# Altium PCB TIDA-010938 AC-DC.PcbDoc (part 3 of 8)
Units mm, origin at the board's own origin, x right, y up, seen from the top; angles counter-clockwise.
Board outline 280 x 180.15 mm, 4 copper layers (Top Layer, Layer 1, Layer 2, Bottom Layer), stack 1.787 mm thick; 723 components, 427 nets, 2244 pads, 2295 vias.
Unrouted connection lines stored in the file: 17.
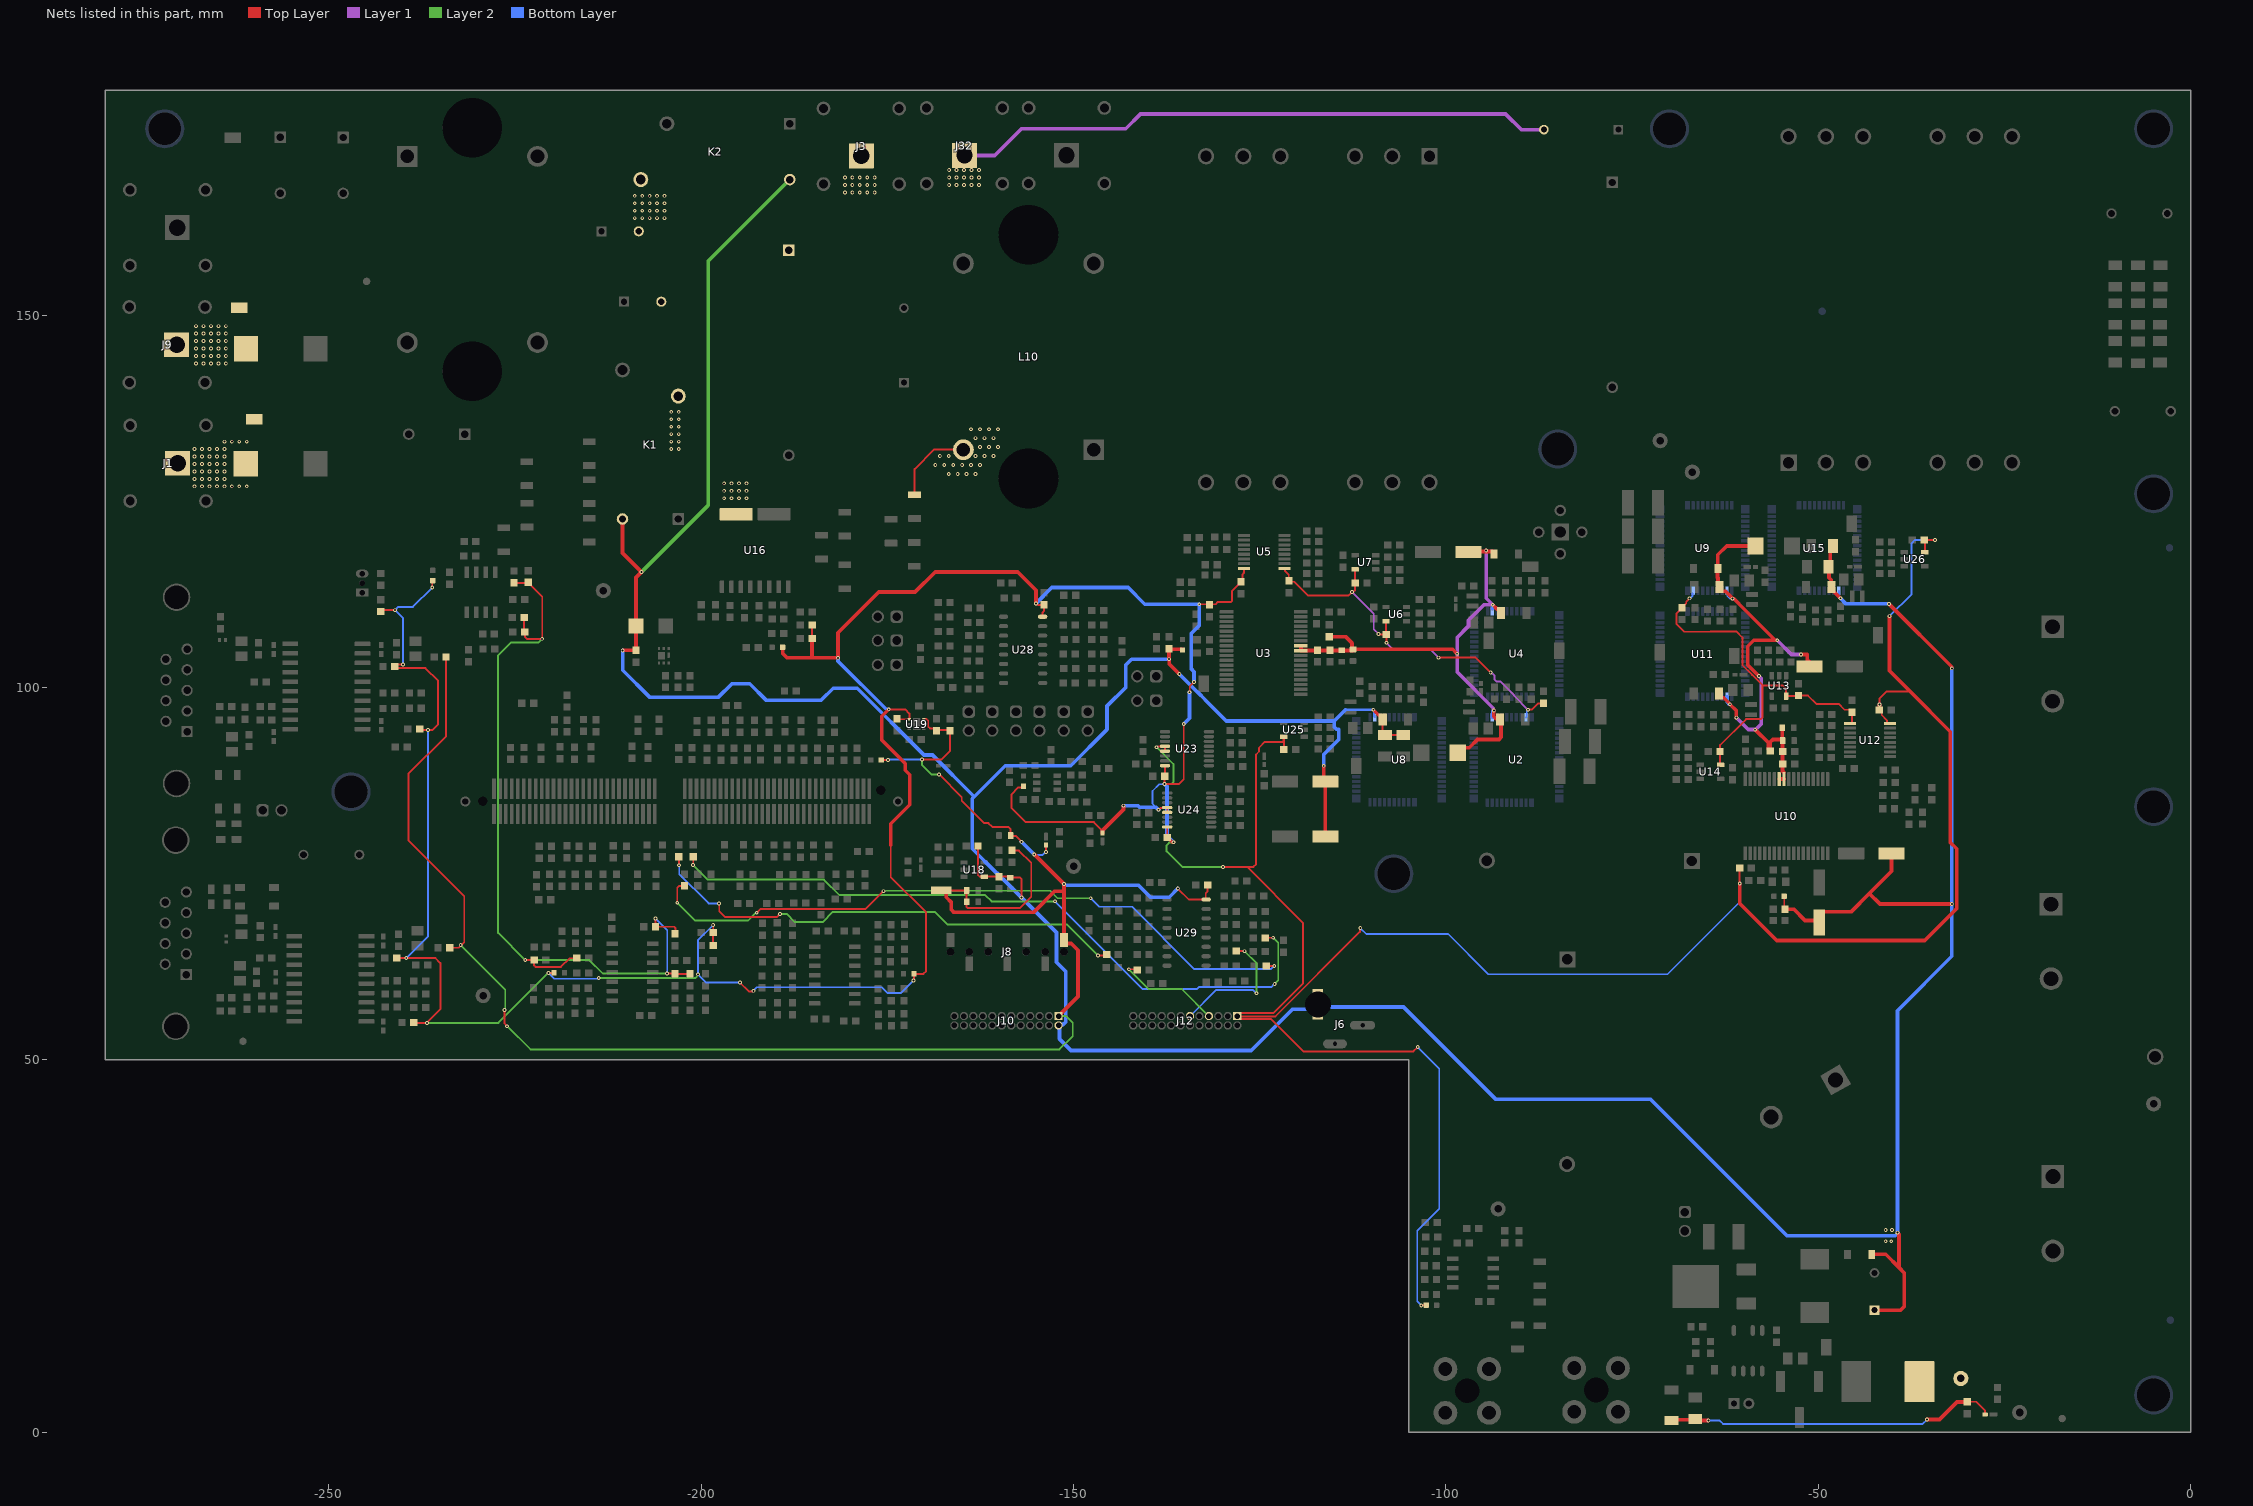
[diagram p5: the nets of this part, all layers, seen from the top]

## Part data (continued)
C217 C221 C233 C237: library part CMP-0007220-4, "CAP, CERM, 47 pF, 50 V, +/- 5%, C0G/NP0, 0603", Cap_Case=0603, Manufacturer=MuRata, Supplier Part Number 1=490-1419-1-ND, TempCo=C0G/NP0, Tolerance_%=5%, Value1=Unknown, Value2=50V, ValueDisplayed=47pF
C220 C236: library part CMP-0006987-4, "CAP, CERM, 4700 pF, 50 V, +/- 10%, X7R, 0603", Cap_Case=0603, Manufacturer=Kemet, Supplier Part Number 1=399-5337-1-ND, TempCo=X7R, Tolerance_%=10%, Value1=Unknown, Value2=50V, ValueDisplayed=4700pF
C241 C242: library part CMP-0037193-1, "5 µF Film Capacitor 900V Polypropylene (PP), Metallized Radial", Digikey Part Number=399-C4AKOBU4500A31J-ND, Manufacturer=Kemet, Mouser Part Number=80-C4AKOBU4500A31J, Operating Temperature Range="-55°C to +135°C", Tolerance_%=5%, ValueDisplayed=5uF
C243 C244: library part CMP-0009613-2, "CAP, CERM, 2200 pF, 300 V, +/- 20%, E, TH, 2- Leads, Body 9x7mm, Pin Spacing 7.5mm", Cap_Case=9x7x9mm, Manufacturer=MuRata, Supplier Part Number 1=DE6E3KJ222MN3A-ND, TempCo=E, Tolerance_%=20%, Value1=Unknown, Value2=300V, ValueDisplayed=2200pF
D1 D7: library part CMP-0095009-1, "Diode Silicon Carbide Schottky 1200 V 2A (DC) Surface Mount DO-214AA", Digikey Part Number=1242-1170-1-ND, Forward Current=2A, Manufacturer="GeneSiC Semiconductor", Max Surge Forward Current=20A, Mouser Part Number=905-GB02SLT12-214, Operating Temperature Range="-55°C to +175°C", Peak Reverse Current=1uA, ValueDisplayed=122pF
D2 D8 D19: library part CMP-0005769-4, "Diode, Zener, 16 V, 500 mW, AEC-Q101, SOD-123", Manufacturer="Diodes Inc.", Power_W=500mW, Value1=0.5W
D4 D10 D16 D17 D18 D23 D24 D25 D26 D27 D28: library part CMP-0093310-1, "Standard LEDs - SMD Green TOPLED E 1608", Color=Green, Forward Current=2mA, Manufacturer="Osram Opto", Mouser Part Number=720-KGDELLS122A4849, Operating Temperature Range="-40°C to +110°C"
D13: library part CMP-0028389-2, "Diode, Schottky, 60 V, 1 A, SMA", Manufacturer="Diodes Inc.", Value1=1A, Value2=0.7V
D14: library part CMP-0029001-2, "Diode, Ultrafast, 100 V, 0.15 A, SOD-123", Manufacturer="Diodes Inc.", Value1=0.15A, Value2=1.25V
D15: library part CMP-0029162-2, "Diode, Ultrafast, 600 V, 1 A, AEC-Q101, SMAF", Manufacturer="Fairchild Semiconductor", Value1=1A, Value2=1.7V
D20: library part CMP-0076883-2, "Diode, Switching, 800 V, 3 A, SMC", Manufacturer=Vishay-Semiconductor, Value1=3A, Value2=1.3V
F1 F2: library part CMP-0122960-1, "25 A 250 V AC 80 V DC Fuse Board Mount (Cartridge Style Excluded) Surface Mount 2-SMD, Square End Block", Digikey Part Number=SF-3812F2500T-2CT-ND, Fuse Current=25A, Fuse Interrupt Dc Current=130A, Manufacturer=Bourns, Mouser Part Number=652-SF-3812F2500T-2, Operating Temperature Range="-55°C to +125°C"
FB2 FB4 FB6 FB7 FB8 FB9 FB11 FB12 FB14: library part CMP-0037505-1, "600 Ohms @ 100 MHz 1 Power, Signal Line Ferrite Bead 0603 (1608 Metric) 1A 200mOhm", Digikey Part Number=MH1608-601YCT-ND, Impedance At Frequency="600Ω @ 100MHz", Manufacturer=Bourns, Mouser Part Number=652-MH1608-601Y, Operating Temperature Range="-55°C to +125°C", Test Frequency=100MHz, Tolerance_%=25%
FB18 FB23: library part CMP-0041881-1, "Chip Ferrite Bead, 0402, 330Ω @ 100MHz, 0.205Ω, 25%, 1.1A", Impedance At Frequency="330Ω @ 100MHz", Manufacturer=Murata, Operating Temperature Range="-55°C to +125°C", Test Frequency=100MHz, Tolerance_%=25%
FID1 FID2 FID3 FID4 FID5 FID6: library part CMP-0077181-1, "Fiducial mark.  There is nothing to buy or mount.", Manufacturer=N/A
J1 J32: library part CMP-0098295-2, "Banana Test Connector, 4mm, Socket, PCB Mount, 24 A, 1 kV, Gold Plated Contacts, Blue", Current_A=24A, Manufacturer="CLIFF Electronic Components", Operating Temperature Range="-40°C to +80°C", Voltage_V=1kV
J2 J31: library part CMP-0098294-2, "Banana Test Connector, Socket, PCB Mount, 24 A, 1 kV, Gold Plated Contacts, Green", Current_A=24A, Digikey Part Number=4654-FCR7350G-ND, Manufacturer="CLIFF Electronic Components", Operating Temperature Range="-40°C to +80°C", Voltage_V=1kV
J3 J9: library part CMP-0032021-2, "Banana Jack Connector Standard Banana Solder Black", Current_A=24A, Digikey Part Number=4654-FCR7350B-ND, Manufacturer="CLIFF Electronic Components", Operating Temperature Range="-40°C to +80°C", Voltage_V=1kV
J4 J5 J7 J13 J14 J16 J20 J21 J22 J23 J24 J25 J26: library part CMP-0054794-2, "Header, 2.54 mm, 2x1, Gold, TH", Color=Black, Manufacturer="Wurth Elektronik", Supplier Part Number 1=732-5315-ND
J6: library part CMP-0040211-1, "Power Barrel Connector Jack 2.10mm ID (0.083\"), 5.50mm OD (0.217\") Through Hole", Current_A=3A, Digikey Part Number=732-5931-ND, Manufacturer="Wurth Electronics", Mouser Part Number=710-694106402002, Operating Temperature Range="-40°C to +85°C", Voltage_V=30V
J8: library part CMP-0095208-1, "7 Position Receptacle, Bottom Entry Connector 0.100\" (2.54mm) Surface Mount Gold", Current_A=5.2A, Digikey Part Number=SSM-107-L-SV-BE-ND, Manufacturer=Samtec, Mouser Part Number=200-SSM107LSVBE, Operating Temperature Range="-55°C to +125°C", Voltage_V=572V
J10 J12: library part CMP-0003796-1, "Conn Shrouded Header (4 Sides) HDR 24 POS 1.27mm Solder ST Top Entry Thru-Hole Tube", Digikey Part Number=SHF-112-01-L-D-TH-ND, Manufacturer=Samtec, Mouser Part Number=200-SHF11201LDTH, Operating Temperature Range="-55°C to +125°C"
J11: library part CMP-0003814-2, "C2000 controlCARD-120HSEC connector, SMT", Manufacturer=Samtec
J15 J17: library part CMP-0054820-2, "Receptacle, D-Sub, 9 Position, R/A, TH", Color=Black, Current_A=3A, Manufacturer="Wurth Elektronik", Supplier Part Number 1=16T0655, Voltage_V=125V
J18 J19: library part CMP-0078526-1, "Power Element Bush, M3, TH", Current_A=50A, Manufacturer="Wurth Elektronik", Supplier Part Number 1=732-10882-1-ND
J27: library part CMP-0089221-2, "Test Clip, Lead, Probe Adapter for use with LeCroy Passive Probes", Digikey Part Number=PK007-015-ND, Manufacturer="Teledyne Lecroy", Mouser Part Number=940-PK007-015, Operating Temperature Range=to
K1 K2: library part CMP-0093993-1, "General Purpose Relay SPST-NO (1 Form A) 12VDC Coil Through Hole", Coil Current_A=44.1mA, Coil Power_W=530mW, Coil Resistance=272Ω, Coil Voltage_VDC=12V, Contact Rating_A=20A, Digikey Part Number=39-G5PZ-1A-EDC12-ND, Manufacturer=Omron, Mouser Part Number=653-G5PZ-1A-EDC12, Operating Temperature Range="-40°C to +70°C"
L1 L4: library part CMP-0123013-1, "PFC Inductor 87µH ±10% 35A 13 mΩ", Manufacturer=Bourns, Operating Temperature Range="-40°C to +125°C", Test Frequency=100kHz, Tolerance_%=10%
L2 L3 L5 L6 L7 L9: library part CMP-0089347-1, "4.7µH Unshielded Inductor 1.1A 426mOhm Max 0806 (2016 Metric)", Digikey Part Number=2037-SDEM20161T-4R7MSCT-ND, Manufacturer=Cyntec, Operating Temperature Range="-55°C to +125°C", Test Frequency=1MHz, Tolerance_%=20%
L8 L12 L16 L17: library part CMP-0003349-2, "Ferrite Bead, 1500 ohm @ 100 MHz, 0.5 A, 0603", Manufacturer=MuRata, Supplier Part Number 1=490-5216-1-ND, Value1="0.5 ohm", Value2=0.5A, ValueDisplayed="1500 ohm"
L10 L11: library part CMP-0123012-1, "Common Mode Choke 4mH ±30%", Manufacturer="Kaschke Components", Operating Temperature Range="-25°C to +125°C", Tolerance_%=30%
L13: library part CMP-0123259-1, "Shielded SMD Power Inductor 220uH 2A 240mOhm 12.0x12.0x10.0mm SMT", Manufacturer=Bourns, Operating Temperature Range="-55°C to +150°C", Test Frequency=1kHz, Tolerance_%=10%
L14: library part CMP-0056744-1, "Inductor, Drum Core, Ferrite, 10 uH, 0.88 A, 0.276 ohm, SMD", Manufacturer=Bourns, Supplier Part Number 1=SRN3015-100MCT-ND, Value1="0.276 ohm", Value2=0.88A, ValueDisplayed=10uH
L25 L31: library part CMP-0084086-1, "100µH @ 100kHz 2 Line Common Mode Choke Surface Mount 5.8 kOhms @ 10MHz 150mA DCR 2Ohm", Digikey Part Number=445-3959-1-ND, Impedance At Frequency="5800Ω @ 10MHz", Manufacturer=TDK, Mouser Part Number=810-ACT45B1012PTL003, Operating Temperature Range="-40°C to +150°C", Test Frequency=100kHz, Tolerance_%=+50/-30%
LBL1: library part CMP-0003625-1, "Thermal Transfer Printable Labels, 0.650\" W x 0.200\" H - 10,000 per roll", Manufacturer=Brady, Supplier Part Number 1=97C5133
LOGO1: library part CMP-0074837-1, "IEC 61010-1 Hot Surface Warning"
LOGO2: library part CMP-0074835-1, "IEC 61010-1 High Voltage Warning"
Logo3: library part CMP-0074844-1
Logo5: library part CMP-0074847-1, "FCC_disclaimer"
Logo6: library part CMP-0074769-1
MP1 MP2 MP3 MP4 MP5 MP6 MP7 MP8 MP12: library part CMP-0040203-1, "Round Spacer Unthreaded Steel 0.059\" (1.50mm)", Digikey Part Number=732-7071-1-ND, Manufacturer="Wurth Electronics", Mouser Part Number=710-9774015960R, Operating Temperature Range="-55°C to +150°C"
Q1: library part CMP-0076725-1, "30-V N-Channel NexFET™ Power MOSFET", Manufacturer="Texas Instruments"
Q2: library part CMP-0001278-3, "MOSFET, N-CH, 800 V, 2.5 A, DPAK", Alternate Manufacturer=None, Manufacturer=STMicroelectronics, Supplier Part Number 1=497-7968-1-ND, Value2="19 nC"
R1 R8 R9 R18 R19 R24 R25 R26 R27 R28 R29 R31 R32 R35 R37 R38 R39 R58 R59 R61 R62 R63 R64 R65 R66 R69 R71 R72 R73 R83 R86 R87 R88 R120 R121 R134 R140 R141 R144 R146 R148 R150 R151 R152 R154 R160 R161 R169 R170 R175 R259 R260 R263 R264 R265 R267 R268 R270 R272 R273 R274 R276 R278 R279 R281 R282 R284 R286 R311 R314 R319 R320 R323: library part CMP-0023572-3, "RES, 56, 0.1%, 0.1 W, 0603", Manufacturer="Susumu Co Ltd", Power_W=100mW, Supplier Part Number 1=RG16P56.0BCT-ND, TempCo="25 ppm/C", Tolerance_%=0.1%, Value2=0.1W, Value_Code=56R0, ValueDisplayed=56
R2 R3 R4 R97 R119 R136 R137 R138 R139 R142 R143 R145 R156 R159 R163 R165: library part CMP-0024479-2, "RES, 7.32 k, 0.1%, 0.1 W, 0603", Manufacturer="Yageo America", Power_W=100mW, TempCo="25 ppm/C", Tolerance_%=0.1%, Value2=0.1W, Value_Code=7k32, ValueDisplayed=7.32k
R5 R23 R33 R34 R36 R50 R68 R99 R125 R126 R130 R131 R133 R135 R147 R149 R153 R155 R157 R158 R162 R164 R166 R167 R168 R171 R172 R173 R237 R238 R239 R252 R253 R254 R256 R297 R298 R299 R300 R301 R302 R303 R304 R305 R306 R307 R308 R310 R318 R328 R329 R330 R331 R332 R335 R336 R337 R338: library part CMP-0023404-3, "RES, 10.0 k, 0.1%, 0.1 W, 0603", Manufacturer="Susumu Co Ltd", Power_W=100mW, Supplier Part Number 1=RG16P10.0KBCT-ND, TempCo="25 ppm/C", Tolerance_%=0.1%, Value2=0.1W, Value_Code=10k0, ValueDisplayed=10.0k
R6: library part CMP-0089579-1, "SENSOR PTC 10K OHM 1% TO92S", Digikey Part Number=296-TMP6131LPGMCT-ND, Manufacturer="Texas Instruments", Max Current=400uA, Mouser Part Number=595-TMP6131LPGM, Operating Temperature Range="-40°C to +150°C", TempCo=6400ppm/°C, Tolerance_%=1%
R7 R41 R53 R55: library part CMP-0018694-3, "RES, 4.7, 5%, 0.75 W, AEC-Q200 Grade 0, 1206", Manufacturer=Vishay-Dale, Power_W=750mW, Supplier Part Number 1=541-4.7UACT-ND, TempCo="200 ppm/C", Tolerance_%=5%, Value2=0.75W, Value_Code=4R70, ValueDisplayed=4.7
R10 R30 R40 R44 R60 R74: library part CMP-0023577-3, "RES, 56.0 k, 0.1%, 0.1 W, 0603", Manufacturer="Susumu Co Ltd", Power_W=100mW, Supplier Part Number 1=RG16P56.0KBCT-ND, TempCo="25 ppm/C", Tolerance_%=0.1%, Value2=0.1W, Value_Code=56k0, ValueDisplayed=56.0k
R11 R13 R46 R47: library part CMP-0022685-3, "RES, 12.0 k, 1%, 0.1 W, 0603", Manufacturer=Panasonic, Power_W=100mW, Supplier Part Number 1=P12.0KHCT-ND, TempCo="100 ppm/C", Tolerance_%=1%, Value2=0.1W, Value_Code=12k0, ValueDisplayed=12.0k
R12 R45: library part CMP-0025200-2, "RES, 38.8 k, 0.5%, 0.1 W, 0603", Manufacturer="Yageo America", Power_W=100mW, TempCo="50 ppm/C", Tolerance_%=0.5%, Value2=0.1W, Value_Code=38k8, ValueDisplayed=38.8k
R14 R48: library part CMP-0023076-5, "RES, 3.01 k, 1%, 0.1 W, 0603", Manufacturer=Yageo, Power_W=100mW, Supplier Part Number 1=311-3.01KHRCT-ND, TempCo="100 ppm/C", Tolerance_%=1%, Value2=0.1W, Value_Code=3k01, ValueDisplayed=3.01k
R15 R49 R84 R85 R90 R104 R105: library part CMP-0023404-1, "RES, 10.0 k, 0.1%, 0.1 W, 0603", Manufacturer="Susumu Co Ltd", Power_W=100mW, Supplier Part Number 1=RG16P10.0KBCT-ND, TempCo="25 ppm/C", Tolerance_%=0.1%, Value2=0.1W, Value_Code=10k0, ValueDisplayed=10.0k
R16: library part CMP-0025771-4, "RES, 2.7 k, 5%, 0.1 W, AEC-Q200 Grade 0, 0603", Manufacturer=Vishay-Dale, Power_W=100mW, Supplier Part Number 1=541-2.7KGCT-ND, TempCo="200 ppm/C", Tolerance_%=5%, Value2=0.1W, Value_Code=2k70, ValueDisplayed=2.7k
R17 R42 R43 R51 R52 R100 R115: library part CMP-0025933-5, "RES, 5.6 k, 5%, 0.1 W, 0603", Manufacturer=Yageo, Power_W=100mW, Supplier Part Number 1=311-5.6KGRCT-ND, TempCo="100 ppm/C", Tolerance_%=5%, Value2=0.1W, Value_Code=5k60, ValueDisplayed=5.6k
R20 R21 R22 R54 R56 R57 R67 R174 R176 R177 R178 R179 R180 R181 R182 R183 R184 R186 R187 R188 R189 R190 R191 R192 R193 R194 R195 R196 R197 R198 R199 R200 R201 R202 R203 R204 R205 R206 R207 R208 R209 R210 R211 R212 R213 R214 R215 R216 R217 R218 R219 R220 R221 R222 R223 R224 R225 R226 R227 R228 R229 R230 R231 R232 R233 R234 R236 R240 R241 R242 R243 R244 R245 R246 R247 R248 R249 R250: library part CMP-0081973-1, "RES, 0, 0%, 0.25 W, AEC-Q200 Grade 0, 0603", Manufacturer=Vishay-Dale, Power_W=250mW, Supplier Part Number 1=541-2779-1-ND, Tolerance_%=0%, Value2=0.25W, Value_Code=0
R70 R76 R102: library part CMP-0025936-5, "RES, 680, 5%, 0.1 W, 0603", Manufacturer=Yageo, Power_W=100mW, Supplier Part Number 1=311-680GRCT-ND, TempCo="100 ppm/C", Tolerance_%=5%, Value2=0.1W, Value_Code=680R, ValueDisplayed=680
R75 R114: library part CMP-0097004-1, "PTCEL Series 500 V 60 Ohm ±30 % Radial Inrush Current Limiter PTC Thermistor", Digikey Part Number=BC3317-ND, Hold Current=120mA, Manufacturer="Vishay Bccomponents", Mouser Part Number=594-PTCEL13R600LBE, Operating Temperature Range="-40°C to +105°C", Tolerance_%=30%
R77 R79 R80 R185 R235 R290 R291 R326 R327: library part CMP-0017399-3, "RES, 169 k, 1%, 0.25 W, AEC-Q200 Grade 0, 1206", Manufacturer=Panasonic, Power_W=250mW, Supplier Part Number 1=P169KFCT-ND, TempCo="100 ppm/C", Tolerance_%=1%, Value2=0.25W, Value_Code=169k
R78 R81 R82: library part CMP-0096768-1, "5 kA Varistor 1 Circuit Through Hole Disc 17mm", Clamping Voltage=730V, Digikey Part Number=118-ISOM5-275-B-L2-ND, Manufacturer=Bourns, Mouser Part Number=652-ISOM5-275-B-L2, Operating Temperature Range="-40°C to +125°C", ValueDisplayed=40pF
R89: library part CMP-0024912-2, "RES, 200, 0.5%, 0.1 W, 0603", Manufacturer="Yageo America", Power_W=100mW, TempCo="50 ppm/C", Tolerance_%=0.5%, Value2=0.1W, Value_Code=200R, ValueDisplayed=200
R91: library part CMP-0024274-3, "RES, 48.1 k, 0.1%, 0.1 W, 0603", Manufacturer="Yageo America", Power_W=100mW, TempCo="25 ppm/C", Tolerance_%=0.1%, Value2=0.1W, Value_Code=48k1, ValueDisplayed=48.1k
R92: library part CMP-0025444-3, "RES, 5.76 k, 0.5%, 0.1 W, 0603", Manufacturer="Yageo America", Power_W=100mW, TempCo="50 ppm/C", Tolerance_%=0.5%, Value2=0.1W, Value_Code=5k76, ValueDisplayed=5.76k
R93: library part CMP-0023520-3, "RES, 33.0 k, 0.1%, 0.1 W, 0603", Manufacturer="Susumu Co Ltd", Power_W=100mW, Supplier Part Number 1=RG16P33.0KBCT-ND, TempCo="25 ppm/C", Tolerance_%=0.1%, Value2=0.1W, Value_Code=33k0, ValueDisplayed=33.0k
R94: library part CMP-0017008-3, "RES, 475 k, 1%, 0.25 W, AEC-Q200 Grade 0, 1206", Manufacturer=Vishay-Dale, Power_W=250mW, Supplier Part Number 1=541-475KFCT-ND, TempCo="100 ppm/C", Tolerance_%=1%, Value2=0.25W, Value_Code=475k
R95: library part CMP-0024711-2, "RES, 15.6 k, 0.5%, 0.1 W, 0603", Manufacturer="Yageo America", Power_W=100mW, TempCo="50 ppm/C", Tolerance_%=0.5%, Value2=0.1W, Value_Code=15k6, ValueDisplayed=15.6k
R96: library part CMP-0025116-2, "RES, 301, 0.5%, 0.1 W, 0603", Manufacturer="Yageo America", Power_W=100mW, TempCo="50 ppm/C", Tolerance_%=0.5%, Value2=0.1W, Value_Code=301R, ValueDisplayed=301
R98: library part CMP-0021846-2, "RES, 0.1, 1%, 0.125 W, 0805", Manufacturer=Panasonic, Power_W=125mW, Supplier Part Number 1=15R1493, TempCo="250 ppm/C", Tolerance_%=1%, Value2=0.125W, Value_Code=R100, ValueDisplayed=0.1
R101: library part CMP-0025877-3, "RES, 1.5 k, 5%, 0.1 W, AEC-Q200 Grade 0, 0603", Manufacturer=Panasonic, Power_W=100mW, Supplier Part Number 1=P1.5KGCT-ND, TempCo="200 ppm/C", Tolerance_%=5%, Value2=0.1W, Value_Code=1k50, ValueDisplayed=1.5k
R103: library part CMP-0023638-3, "RES, 105 k, 0.1%, 0.1 W, 0603", Manufacturer="Yageo America", Power_W=100mW, TempCo="25 ppm/C", Tolerance_%=0.1%, Value2=0.1W, Value_Code=105k
R106: library part CMP-0024922-3, "RES, 20.0 k, 0.5%, 0.1 W, 0603", Manufacturer="Yageo America", Power_W=100mW, TempCo="50 ppm/C", Tolerance_%=0.5%, Value2=0.1W, Value_Code=20k0, ValueDisplayed=20.0k
R107: library part CMP-0025733-4, "RES, 1.5 k, 5%, 0.1 W, AEC-Q200 Grade 0, 0603", Manufacturer=Vishay-Dale, Power_W=100mW, Supplier Part Number 1=541-1.5KGCT-ND, TempCo="200 ppm/C", Tolerance_%=5%, Value2=0.1W, Value_Code=1k50, ValueDisplayed=1.5k
R108 R109 R110: library part CMP-0018815-2, "RES, 560 k, 0.1%, 1 W, 1206", Manufacturer="Vishay Draloric", Power_W=1W, Supplier Part Number 1=541-2316-1-ND, TempCo="25 ppm/C", Tolerance_%=0.1%, Value_Code=560k
R111 R112 R113 R116 R117 R118 R122 R123 R124 R127 R128 R129: library part CMP-0018805-2, "RES, 1.00 M, 0.1%, 1 W, 1206", Manufacturer="Vishay Draloric", Power_W=1W, Supplier Part Number 1=541-2320-1-ND, TempCo="25 ppm/C", Tolerance_%=0.1%, Value_Code=1M00, ValueDisplayed=1.00M
R132: library part CMP-0089217-1, "100 kOhms 0.25W, 1/4W Gull Wing Surface Mount Trimmer Potentiometer Cermet 12 Turn Top Adjustment", Digikey Part Number=3269W-1-104LF-ND, Manufacturer=Bourns, Mouser Part Number=652-3269W-1-104LF, Operating Temperature Range="-65°C to +150°C", Power_W=250mW, TempCo=100ppm/°C, Tolerance_%=10%
R280 R287 R288 R289: library part CMP-0025431-3, "RES, 59.7, 0.5%, 0.1 W, 0603", Manufacturer="Yageo America", Power_W=100mW, TempCo="50 ppm/C", Tolerance_%=0.5%, Value2=0.1W, Value_Code=59R7, ValueDisplayed=59.7
R312 R316 R321 R325: library part CMP-0089632-1, "0 Ohms Jumper 0.125W, 1/8W Chip Resistor 0805 (2012 Metric) Automotive AEC-Q200 Thick Film", Digikey Part Number=RMCF0805ZT0R00CT-ND, Manufacturer="Stackpole Electronics", Operating Temperature Range="-55°C to +155°C", Power_W=125mW, TempCo=200ppm/°C
TP1 TP4 TP5 TP6 TP7 TP9 TP11 TP16 TP17 TP18 TP21 TP22 TP23: library part CMP-0003968-1, "Test Point, SMT", Manufacturer=Harwin, Supplier Part Number 1=952-2664-1-ND
TP2 TP3 TP12 TP14 TP15 TP19 TP20: library part CMP-0055138-2, "Test Point, Miniature, Black, TH", Color=Black, Manufacturer="Keystone Electronics", Supplier Part Number 1=36-5001-ND
TP8: library part CMP-0055140-2, "Test Point, Miniature, Orange, TH", Color=Orange, Manufacturer="Keystone Electronics", Supplier Part Number 1=36-5003-ND
TP10: library part CMP-0055154-1, "Test Point, Miniature, Blue, TH", Color=Blue, Manufacturer=Keystone, Supplier Part Number 1=36-5117-ND
TP13: library part CMP-0055142-2, "Test Point, Compact, Red, TH", Color=Red, Manufacturer="Keystone Electronics", Supplier Part Number 1=36-5005-ND
U2 U4 U8 U9 U11 U15: library part CMP-0089967-3, "650-V 30-mΩ GaN FET with Integrated Driver and Protection", Manufacturer="Texas Instruments", Max Supply Voltage=18V, Min Supply Voltage=7.5V, Nominal Supply Current=16mA, Operating Temperature Range="-40°C to +125°C", Output Voltage=520V
U3 U10: library part CMP-0033793-2, "Automotive 1.5-W, 12-V VIN / 12-VOUT, 15-V VIN / 15-V VOUT, HighDensity, > 5-kVRMS, Isolated DC/DC Module", Manufacturer="Texas Instruments", Max Supply Voltage=18V, Min Supply Voltage=9V, Nominal Supply Current=200-270mA, Operating Temperature Range="-40°C to +150°C", Output Voltage=10-18V, Switching Frequency=18MHz
U5 U12: library part CMP-0091060-1, "Automotive, robust EMC, six-channel, 4/2, reinforced digital isolator 16-SSOP -40 to 125", Digikey Part Number=296-ISO7762FQDBQRQ1CT-ND, Manufacturer="Texas Instruments", Max Supply Voltage=5.5V, Min Supply Voltage=2.25V, Mouser Part Number=595-ISO7762FQDBQRQ1, Nominal Supply Current=2.1-25.7mA, Operating Temperature Range="-40°C to +125°C"
U6 U7 U13 U14 U25 U26: library part CMP-0051571-2, "Single 2-Input Positive-AND Gate, DBV0005A, SMALL T&R", Alternate Manufacturer="Texas Instruments", F @ Nom Voltage(Max)(Mhz)=150, Generic Part Number=SN74LVC1G08, ICC @ Nom Voltage(Max)(mA)=0.01, Operating Temperature Range(C)="-40 to 125,-40 to 85", Rating=Catalog, tpd @ Nom Voltage(Max)(ns)=4.5,6,4,5, Voltage(Nom)(V)=1.8,2.5,3.3,5
U16: library part CMP-0096051-1, Manufacturer="Texas Instruments", Operating Temperature Range=to
U17: library part CMP-0067230-2, "Constant-Voltage, Constant-Current PWM Controller with Primary-Side Regulation, D0007A (SOIC-7)", Alternate Manufacturer="Texas Instruments", Alternate PartNumber=UCC28710D
U18: library part CMP-0067067-1, "17V Input, 500mA Synchronous Step-Down Regulator in SOT-23 with Advanced Eco-Mode(TM), DBV0005A (SOT-23-5)", Alternate Manufacturer="Texas Instruments", Alternate PartNumber=TPS560200DBVT
U19: library part CMP-0013427-7, "500mA LDO, DRV0006A (WSON-6)", Alternate Manufacturer="Texas Instruments"
U20 U32: library part CMP-0097119-1, "Precision, Zero-Drift, Zero-Crossover, True Rail-to-Rail, Input/Output Operational Amplifiers", Digikey Part Number=296-OPA2388IDRCT-ND, Input Bias Current=0.00003uA, Input Offset Voltage=0.00025mV, Manufacturer="Texas Instruments", Max Dual Supply Voltage=2.75V, Max Supply Voltage=5.5V, Min Dual Supply Voltage=1.25V, Min Supply Voltage=2.5V, Mouser Part Number=595-OPA2388IDR, Nominal Supply Current=1.7-1.9mA, Operating Temperature Range="-40°C to +125°C", Output Current Per Channel=30-60mA, Voltage Gain=126-148dB
U21 U22: library part CMP-0097120-1, "Op Amp Quad Zero Drift Amplifier R-R I/O ±2.75V/5.5V 14-Pin SOIC T/R", Digikey Part Number=296-53511-1-ND, Input Bias Current=0.00003uA, Input Offset Voltage=0.00225mV, Manufacturer="Texas Instruments", Max Dual Supply Voltage=2.75V, Max Supply Voltage=5.5V, Min Dual Supply Voltage=1.25V, Min Supply Voltage=2.5V, Mouser Part Number=595-OPA4388IDR, Nominal Supply Current=1.7-1.9mA, Operating Temperature Range="-40°C to +125°C", Output Current Per Channel=60mA, Voltage Gain=148dB
U23 U24: library part CMP-0045028-1, "Data Selectors/Multiplexers With 3-State Outputs, PW0016A, TUBE", F @ Nom Voltage(Max)(Mhz)=28, Generic Part Number=SN74HC251, ICC @ Nom Voltage(Max)(mA)=0.08, Manufacturer="Texas Instruments", Operating Temperature Range(C)="-40 to 85", Rating=Catalog, tpd @ Nom Voltage(Max)(ns)=51, Voltage(Nom)(V)=3.3,5
U27: library part CMP-0051910-1, "Dual Buffer Gate, DBV0006A, LARGE T&R", F @ Nom Voltage(Max)(Mhz)=150, Generic Part Number=SN74LVC2G34, ICC @ Nom Voltage(Max)(mA)=0.01, Manufacturer="Texas Instruments", Operating Temperature Range(C)="-40 to 125,-40 to 85", Rating=Catalog, tpd @ Nom Voltage(Max)(ns)=8.6,4.4,4.1,3.2, Voltage(Nom)(V)=1.8,2.5,3.3,5
U28 U29: library part CMP-0047247-1, "Hex Buffers And Line Drivers With 3-State Outputs, D0016A, TUBE", F @ Nom Voltage(Max)(Mhz)=28, Generic Part Number=SN74HC365, ICC @ Nom Voltage(Max)(mA)=0.08, Manufacturer="Texas Instruments", Operating Temperature Range(C)="-40 to 85", Rating=Catalog, tpd @ Nom Voltage(Max)(ns)=20, Voltage(Nom)(V)=6
U30: library part CMP-0092023-2, "Reinforced 5-kVRMS Isolated CAN Transceiver with Integrated lowemissions DC-DC Converter", Manufacturer="Texas Instruments", Max Supply Voltage=5.5V, Min Supply Voltage=1.71V, Nominal Supply Current=0.3-124mA, Operating Temperature Range="-40°C to +105°C"
U31: library part CMP-0089988-1, "Reinforced 5-kVRMS Isolated RS-485/RS-422 Transceiver With Integrated Low Emissions DC-DC Converter", Manufacturer="Texas Instruments", Max Supply Voltage=5.5V, Min Supply Voltage=1.71V, Operating Temperature Range="-40°C to +105°C"
ZZ1: library part CMP-0003616-3
ZZ2: library part CMP-0077236-1
ZZ3: library part CMP-0077237-1
ZZ4: library part CMP-0077238-1

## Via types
v1: diameter 0.508, hole 0.254, Top Layer to Bottom Layer, tented both sides, 2041 vias
v2: diameter 0.508, hole 0.254, Top Layer to Bottom Layer, 252 vias
v3: diameter 0.5, hole 0.2, Top Layer to Bottom Layer, 2 vias

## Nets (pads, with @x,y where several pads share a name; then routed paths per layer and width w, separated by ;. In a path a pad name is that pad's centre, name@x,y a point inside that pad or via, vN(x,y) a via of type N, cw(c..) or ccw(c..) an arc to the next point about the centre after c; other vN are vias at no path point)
1V65_REF: C6.2 C45.2 C143.1 C155.1 C165.2 R23.2 R36.2 R136.2 R156.2 R170.2 | length 107.8
  Top Layer w0.25: C45.2@-225.142,114.033 -223.264,114.033 R36.2@-223.2,114.097 -223.2,114.072 -221.332,112.203 v1(-221.332,106.528) -223.412,106.528 -223.618,106.733 -223.618,107.361 R23.2@-223.681,107.424 -223.758,107.5 C6.2@-223.758,109.366 ; v1@-223.425,63.4 R136.2@-222.425,63.4 -222.45,63.375 -222.45,62.7 -222.225,62.475 -218.825,62.475 -217.65,63.65 C143.1@-216.775,63.65 ; v1@-206.125,68.95 -206.118,68.943 C165.2@-206.118,67.871 -203.621,67.871 -203.45,67.7 R170.2@-203.45,67.15 ; v1@-204.525,61.575 -204.52,61.58 C155.1@-203.499,61.58 -203.444,61.525 R156.2@-201.475,61.525
  Layer 2 w0.25: v1(-221.332,106.528) -221.84,106.019 -225.548,106.019 -227.25,104.317 -227.25,67.05 v1(-223.6,63.4) -214.987,63.4 -213.187,61.6 v1@-204.6,61.6
  Bottom Layer w0.25: v1(-206.125,69) -204.546,67.421 -204.546,61.719 -204.565,61.7 v1@-204.6,61.7
  other v1: -204.575,61.6
3V3_HVN: C38.1 C84.2 C115.1 C123.2 C161.2 C169.1 C176.1 C185.1 C186.1 C201.2 D18.2 FB6.1 FB7.1 FB8.1 FB11.1 FB12.1 FB14.1 J12.1 L12.1 L17.1 R5.2 R11.1 R47.1 R91.1 R166.1 R310.2 R318.2 U5.16 U12.16 U19.1 U23.12 U23.13 U23.16 U24.12 U24.13 U24.16 U25.5 U26.5 U28.16 | length 706.8
  Top Layer w0.25: R5.2@-243,110.2 -242.825,110.375 v1(-241.075,110.375) ; R318.2@-240.842,63.678 -235.678,63.678 -235,63 -235,56.802 v1@-236.902,54.9 ; v1@-240.1,103.1 -240.794,103.1 R310.2@-241.1,102.794 -240.906,102.6 -237,102.6 -235.3,100.9 -235.3,95.046 -236.046,94.3 L12.1@-237.9,94.3 ; L17.1@-238.556,55.033 -238.479,54.956 v1(-236.813,54.956) ; v1(-236.089,113.411) -236.089,114.266 FB14.1@-236.023,114.333 ; v1(-220.5,61.675) -220.488,61.687 -219.787,61.687 FB8.1@-219.75,61.65 ; R166.1@-198.381,65.394 C161.2@-198.381,67.13 ; v1(-198.375,68.125) -198.375,67.2 C161.2@-198.35,67.175 ; v1(-194.775,60.375) -193.6,59.2 v1@-193.1,59.2 ; C115.1@-185.096,106.6 R91.1@-185.096,108.373 ; v1(-174.808,97.064) -172.6,97.064 -172.035,96.499 U19.1@-172.035,95.726 -173.651,95.726 C123.2@-173.725,95.801 ; -174.54,78.813 -174.54,74.54 -169.8,69.8 -169.8,61.9 -170.146,61.554 FB7.1@-171.426,61.554 v1@-171.426,60.726 ; FB11.1@-156.725,86.725 -156.869,86.581 -157.394,86.581 -158.35,85.625 -158.35,83.85 -156.425,81.925 -147.26,81.925 D18.2@-146.117,80.783 ; v1(-155.049,111.273) -154.987,111.273 -154.784,111.07 C201.2@-154.204,111.07 ; U28.16@-154.05,109.595 U28.16@-154.15,109.495 -154.15,110.057 -153.971,110.236 C201.2@-153.971,111.125 ; v1(-138.85,91.975) -138.78,91.975 -138.693,92.062 -138.162,92.062 U23.12@-138.15,92.05 ; v1(-138.6,83.588) -138.53,83.588 -138.281,83.837 -137.463,83.837 U24.12@-137.425,83.875 U24.13@-137.425,83.225 ; v1(-137.775,87.025) -135.875,87.025 -135.2,87.7 v1(-135.2,95.1) ; v1@-137.775,87.075 -137.775,88.05 C169.1@-137.75,88.075 ; C169.1@-137.725,88.225 U23.16@-137.725,89.5 ; U23.13@-137.725,91.425 U23.13@-137.725,91.45 U23.12@-137.725,92.1 ; C176.1@-137.425,80.05 U24.16@-137.425,81.275 ; v1@-136.616,79.165 v1(-136.566,79.214) ; v1@-134.4,99.4 -134.4,100.175 v1(-133.825,100.75) ; v1(-133.125,111.175) -131.9,111.175 R11.1@-131.85,111.225 ; R11.1@-131.725,111.1 -131.661,111.164 -130.936,111.164 -130.619,111.481 -128.87,111.481 -128.723,111.627 -128.723,112.952 -127.5,114.175 C38.1@-127.5,114.2 -127.3,114.4 -127.3,115.2 -127.125,115.375 -127.125,115.525 U5.16@-127.125,115.978 ; v1(-129.95,75.9) -126.7,75.9 ; J12.1@-127.895,55.505 -123.505,55.505 -119.141,51.141 -104.375,51.141 -103.803,51.714 v1(-103.786,51.714) ; C185.1@-121.75,91.625 C185.1@-121.75,91.675 -121.75,92.7 -121.75,93.02 -121.801,93.071 -121.801,92.7 -124.3,92.7 -125.1,91.9 -125.1,91.4 -125.5,91 -125.5,76.25 -125.85,75.9 -126.7,75.9 ; v1(-111.5,67.7) -111.549,67.651 -111.549,67.176 -122.9,55.825 -127.745,55.825 -127.9,55.98 -127.58,56.3 -123.125,56.3 -119.2,60.225 -119.2,68.4 -126.7,75.9 ; v1(-103.315,17.044) -103.302,17.056 -102.664,17.056 FB12.1@-102.652,17.069 ; v1@-60.59,73.696 R47.1@-60.59,75.746 ; C84.2@-42.005,96.806 -41.688,96.806 -41.503,96.621 -41.503,96.303 -40.799,95.599 -40.799,95.246 -40.719,95.166 U12.16@-40.365,95.166 ; v1(-41.79,97.721) -41.79,98.56 -40.904,99.446 -37.67,99.446 ; C186.1@-35.79,119.821 C186.1@-35.765,119.796 ; U26.5@-35.715,118.221 -35.715,119.746 C186.1@-35.765,119.796 ; v1(-34.365,119.796) C186.1@-35.765,119.796
  Top Layer w0.5: FB6.1@-189.05,105.4 -189.05,104.55 -188.474,103.974 -185.25,103.974 ; C115.1@-185.096,106.595 -185.096,104.128 -185.25,103.974 ; v1(-181.606,103.978) -181.607,103.977 -182.107,103.977 -182.11,103.974 -185.25,103.974 ; v1@-181.606,103.981 -181.606,107.341 -176.145,112.801 -171.268,112.801 -168.57,115.5 -157.5,115.5 -155.049,113.049 v1(-155.049,111.273) ; v1(-174.808,97.064) -175.75,96.122 -175.75,92.929 -172.596,89.775 -172.596,88.871 -172,88.275 -172,84.25 -174.54,81.71 -174.54,78.813 ; D18.2@-146.117,80.452 -146.117,80.783 -143.298,83.602 -143.298,84.127 v1(-143.296,84.129) ; C176.1@-137.425,79.875 -137.4,79.875 -136.741,79.216 -136.568,79.216 v1(-136.566,79.214) ; v1(-60.565,73.696) -60.565,70.996 -55.59,66.021 -35.74,66.021 -31.436,70.325 -31.436,78.346 -32.29,79.2 -32.29,94.067 -37.67,99.446 -40.465,102.242 v1(-40.465,109.571) ; C84.2@-41.84,96.971 -41.792,97.019 -41.792,97.719 v1(-41.79,97.721)
  Layer 2 w0.25: v1@-236.813,54.966 -227.209,54.966 v1(-220.5,61.675) ; v1(-213.734,60.986) -200.814,60.986 v1@-200.4,61.4 ; v1(-138.85,91.975) -136.6,89.725 -136.6,87.3 -136.875,87.025 v1@-137.656,87.025 ; v1(-136.566,79.214) -136.616,79.165 -137.16,79.165 -137.499,78.826 -137.499,77.999 -135.4,75.9 v1(-129.95,75.9)
  Bottom Layer w0.25: v1(-240,103.1) -240,109.3 v1(-241.075,110.375) -240.636,110.814 -238.686,110.814 v1(-236.089,113.411) ; v1@-239.5,63.7 -236.675,66.525 v1(-236.675,94.275) ; v1(-220.5,61.675) -219.725,60.9 v1@-213.7,60.9 ; v1@-198.4,68.1 -200.434,66.066 v1(-200.434,61.486) -199.322,60.375 v1(-194.775,60.375) ; v1(-192.975,59.275) -192.5,59.75 -175.75,59.75 -175,59 -173.15,59 -172.4,59.75 v1(-171.475,60.675) ; -138.945,83.945 -139.4,84.4 -139.4,86.1 -138.5,87 v1@-137.8,87 ; v1(-111.5,67.7) -110.7,66.9 -99.7,66.9 -94.3,61.5 -70.261,61.5 -60.565,71.196 v1@-60.565,73.529 ; v1(-103.786,51.714) -100.91,48.838 -100.91,29.997 -103.859,27.049 -103.859,17.6 v1@-103.302,17.044 ; v1(-40.465,109.571) -37.5,112.536 -37.5,119.361 -37.065,119.796 v1(-34.365,119.796)
  Bottom Layer w0.5: v1(-181.606,103.978) -181.606,103.53 -175.142,97.066 -174.81,97.066 v1(-174.808,97.064) ; v1(-155.049,111.273) -152.911,113.411 -142.661,113.411 -140.425,111.175 v1(-133.125,111.175) -133.125,108.329 -134.179,107.275 -134.179,102.464 -133.825,102.11 v1(-133.825,100.75) ; v1(-143.296,84.129) -141.348,84.129 -141.119,83.9 -138.914,83.9 -138.602,83.588 v1(-138.6,83.588) ; v1@-137.775,87.023 -137.45,86.698 -137.45,80.098 v1(-136.566,79.214) ; v1(-135.2,95.1) -134.425,95.875 v1(-134.425,99.35)
  other v1: -239.575,63.675
5V_HVN: C120.1 C122.2 C124.1 C126.1 C203.1 D17.2 FB9.1 J8.1 J10.1 L8.1 L14.2 L16.1 R103.1 R105.1 U19.6 U29.16 | length 273.2
  Top Layer w0.25: L8.1@-234.242,104.064 -234.242,93.458 -239.3,88.4 -239.3,79.5 -231.8,72 -231.8,65.8 -232.229,65.371 -232.542,65.058 L16.1@-233.719,65.058 ; v1(-226.374,56.717) -226.374,54.887 -226,54.513 v1@-226,54.5 ; FB9.1@-175.81,90.264 v1@-174.861,90.264 ; v1(-170.351,90.347) -167.713,90.347 -166.6,91.46 R105.1@-166.6,94.2 -166.676,94.276 -168.596,94.276 -168.82,94.5 -169.25,94.5 -169.5,94.75 -169.5,95.5 -169.75,95.75 -170.061,95.75 U19.6@-170.085,95.726 ; v1(-168.046,88.33) -164.998,85.283 -164.998,84.798 -162,81.8 -161.429,81.8 -160.9,81.271 -158.742,81.271 -158.455,80.983 C126.1@-158.455,80.121 ; L14.2@-167.8,72.747 L14.2@-167.766,72.781 ; L14.2@-166.89,72.755 C120.1@-164.42,72.755 ; C124.1@-164.362,71.231 -164.362,70.521 -164.215,70.375 -157.225,70.375 -155.675,71.925 -155.675,76.45 -157.325,78.1 -158.275,78.1 R103.1@-158.325,78.15 ; C124.1@-164.362,71.262 C120.1@-164.362,72.755 ; C126.1@-158.36,80.051 -157.701,80.051 v1@-157,79.35 ; v1@-153.7,78 D17.2@-153.7,78.7 ; -151.445,69.915 -151.28,70.08 ; v1(-136.002,72.996) -135.996,72.996 -134.535,71.535 U29.16@-132.2,71.535 ; U29.16@-132.25,71.625 -132.25,72.4 -131.993,72.657 C203.1@-131.993,73.504 ; C203.1@-132.093,73.743 C203.1@-132.075,73.725
  Top Layer w0.5: L14.2@-166.89,72.755 -166.916,72.781 L14.2@-167.766,72.781 -167.349,72.781 -167.099,72.531 -167.099,71.824 -166.4,71.125 -166.4,70.15 -166.056,69.806 -155.387,69.806 -152.545,72.648 -151.28,72.648 ; v1(-155.275,77.575) v1(-155.275,77.575) -155.249,77.573 v1(-151.28,73.605) -151.28,72.648 ; J10.1@-152.015,55.89 -149.4,58.505 -149.4,64.72 -150.313,65.633 -151.02,65.633 J8.1@-151.02,65.838 ; J8.1@-151.28,66.105 -151.28,70.08 -151.28,72.648
  Layer 2 w0.25: v1(-232.274,65.417) -226.3,59.443 v1@-226.3,56.7 ; v1@-226,54.5 -222.9,51.4 -151.9,51.4 -150.1,53.2 -150.1,55 -150.99,55.89 J10.1@-152.015,55.89 ; v1(-170.351,90.347) -170.324,90.32 -170.324,89.576 -169.078,88.33 v1(-168.046,88.33)
  Bottom Layer w0.25: v1(-174.9,90.275) -174.864,90.311 -170.387,90.311 v1(-170.351,90.347) ; v1@-155.1,77.5 -154.17,77.5 -153.77,77.9 v1(-153.7,77.9)
  Bottom Layer w0.5: v1(-156.975,79.275) v1(-155.275,77.575) ; v1(-151.28,73.605) -151.278,73.605 -151.13,73.457 -141.266,73.457 -139.655,71.846 -137.152,71.846 v1(-136.002,72.996)
  other v1: -226.074,54.517
5V_SW1: C12.1 C39.1 C43.1 C47.1 U2.51 U5.1 U6.5 U7.5 | length 52.2
  Top Layer w0.25: U5.1@-121.675,115.978 -121.669,115.978 -121.6,115.908 -121.6,115.6 -121.1,115.1 C39.1@-121.1,114.3 -120.996,114.196 -120.396,114.196 -118.55,112.35 -113.05,112.35 v1(-112.6,112.8) ; v1@-112.525,112.725 -112.225,113.025 C47.1@-112.225,114.05 ; C47.1@-112.2,114.1 U7.5@-112.2,115.85 ; v1@-109.15,107.075 -109.1,107.125 -108.025,107.125 C43.1@-108,107.1 v2(-108,106) ; U6.5@-108.05,108.9 -108.05,107.325 C43.1@-108.025,107.3 ; v2(-101,104) -96,104 v2(-94,102) ; v1(-89,97) -88.951,97.049 -88.426,97.049 -87.625,97.85 -87.25,97.85 -87.2,97.9 C12.1@-87.1,97.9
  Layer 1 w0.25: v1(-112.6,112.8) -109.7,109.9 -109.7,107.825 v1(-109.05,107.175) ; v2(-108,106) -107,105 -102,105 v2(-101,104) ; v2(-94,102) -93.93,102 -93.801,101.871 -93.746,101.871 -93.51,101.635 -93.51,101.104 -93.2,100.794 -92.669,100.794 -90.859,98.984 -90.859,98.882 -89,97.023 v1(-89,97)
  Bottom Layer w0.25: U2.51@-89.3,95.95 -89.15,96.1 -89.15,96.78 -89,96.93 v1(-89,97)
5V_SW2: C44.1 C58.1 C85.2 C91.1 U9.51 U12.1 U13.5 U14.5 | length 52.1
  Top Layer w0.25: C58.1@-68.29,110.721 -68.29,110.696 -69.04,109.946 -69.04,108.507 -68.017,107.483 -64.5,107.483 -64.492,107.492 -60.992,107.492 -60.191,106.691 -60.191,102.979 -58.908,101.696 -58.908,101.69 -57.5,100.282 ; C58.1@-68.115,110.921 -67.739,111.296 -67.739,111.52 v1(-67.295,111.965) ; U14.5@-63.19,89.538 -63.19,92.274 -59.719,95.746 -57.754,95.746 -57.5,96 -57.5,100.282 ; U12.1@-45.765,95.166 -45.58,95.166 -45.5,95.246 C85.2@-45.5,96.7 -45.8,97 -46.5,97 -47.296,97.796 -50.296,97.796 -51.421,98.921 C91.1@-52.69,98.921 -52.69,98.846 U13.5@-54.34,98.846 -54.34,99.84 -54.782,100.282 -57.5,100.282
  Bottom Layer w0.25: v1(-67.295,111.965) -67.225,111.965 -66.931,112.258 -66.89,112.258 U9.51@-66.89,112.621
12V_HVN: C49.1 C94.1 C105.1 C118.1 C119.1 C121.1 C125.2 C238.1 C239.1 C251.1 C252.1 D13.1 D15.2 D16.2 D19.1 FB2.1 FB4.1 J6.1 J10.2 K1.4 K2.4 L13.2 R7.1 R13.1 R41.1 R46.1 R53.1 R55.1 R94.2 R104.1 TP8.1 U8.44 U15.44 U18.4 | length 619.7
  Top Layer w0.25: R104.1@-162.825,78.7 -162.825,74.825 -162.6,74.6 U18.4@-162.3,74.6 ; U18.4@-161.958,74.599 -158.825,74.599 C121.1@-158.65,74.424 ; C121.1@-158.5,74.475 -158.487,74.488 -157.162,74.488 -157,74.325 v1(-157,71.8) ; C49.1@-108.5,95.725 -108.5,93.925 R41.1@-108.2,93.625 R7.1@-105.75,93.625 ; FB4.1@-54.59,71.971 -54.59,70.346 R46.1@-54.465,70.221 ; C119.1@-30.224,4.078 -30.199,4.102 C119.1@-30.023,4.102 ; C119.1@-29.751,4.102 -28.791,4.102 -27.617,2.928 D16.2@-27.617,2.399
  Top Layer w0.5: K1.4@-210.553,122.613 -210.553,118.053 v1(-208,115.5) -208.75,114.75 D13.1@-208.75,108.25 C105.1@-208.75,105.025 ; v1@-210.425,105 C105.1@-208.75,105 ; v1(-135.8,101.8) -137.154,103.154 -137.154,103.779 v1(-137.175,103.8) -137.175,105.075 -137.125,105.125 -135.475,105.125 FB2.1@-135.375,105.025 ; v1(-116.404,89.48) -116.404,87.746 -116.5,87.65 C238.1@-116.2,87.35 -116.2,80.7 C239.1@-116.1,80.6 ; v1(-109.75,97) -109.025,96.275 -108.8,96.275 -108.75,96.225 C49.1@-108.75,95.75 ; C49.1@-108.5,95.725 C49.1@-108.2,95.425 ; D15.2@-69.698,1.592 -69.603,1.687 -66.625,1.687 R94.2@-66.53,1.782 -66.33,1.582 v1(-64.78,1.582) ; R46.1@-54.465,70.221 -53.29,70.221 -51.79,68.721 C251.1@-49.89,68.721 ; C251.1@-49.89,68.421 C251.1@-49.89,68.721 ; R53.1@-48.64,116.196 -48.422,116.414 R55.1@-48.422,118.353 ; R53.1@-48.583,115.513 -48.583,114.721 -48.29,114.428 -48.29,113.496 C94.1@-48.265,113.471 -48.265,113.221 v1@-47.09,112.046 ; D19.1@-42.834,23.899 -40.971,23.899 -39.188,22.116 ; C118.1@-42.471,16.399 -38.971,16.399 -38.471,16.899 -38.471,21.399 -39.188,22.116 ; v1(-40.54,111.221) -32.092,102.772 -32.092,102.572 v1(-32.09,102.571) ; C252.1@-40.19,77.721 -40.19,75.321 -43.165,72.346 ; v1(-39.391,26.803) -39.391,26.801 -39.188,26.598 -39.188,22.116 ; v1(-35.421,1.724) -33.76,1.724 -31.406,4.078 -30.224,4.078 C119.1@-29.751,4.078 ; v1(-32.09,70.921) -41.74,70.921 -43.165,72.346 ; C251.1@-49.89,68.721 -49.89,69.323 -49.34,69.873 -45.638,69.873 -43.165,72.346
  Layer 2 w0.5: v1(-208,115.5) -199.056,124.444 -199.056,157.217 K2.4@-188.091,168.183
  Bottom Layer w0.25: v1(-64.78,1.582) -63.254,1.582 -62.813,1.141 -36.005,1.141 v1(-35.421,1.724) ; U15.44@-47.25,112.971 -47.25,112.205 v1@-47.086,112.041
  Bottom Layer w0.3: -113.5,97 v1(-109.75,97) ; v1@-109.633,96.827 -109.633,96.1 U8.44@-109.558,96.025
  Bottom Layer w0.5: v1(-210.525,104.975) -210.525,102.308 -206.917,98.7 -197.658,98.7 -195.858,100.5 -193.482,100.5 -191.282,98.3 -183.866,98.3 -182.266,99.9 -179.043,99.9 -170.089,90.946 -168.946,90.946 -163.337,85.337 ; -152.3,67 -152.3,63.1 -151.055,61.855 -151.055,55.098 -151.415,54.739 J10.2@-151.896,54.739 ; -152.3,67.1 v1(-157,71.8) -160.276,75.076 -160.326,75.076 -163.6,78.35 -163.6,85.075 -163.337,85.337 ; J10.2@-151.896,54.501 -151.896,52.821 -150.341,51.266 -126.134,51.266 -120.6,56.8 -117.65,56.8 -117.2,57.25 J6.1@-117.2,57.45 -116.85,57.1 -105.7,57.1 -93.3,44.7 -72.514,44.7 -54.213,26.399 -39.7,26.399 -39.393,26.706 -39.393,56.607 -32.09,63.91 v1@-32.09,70.87 ; v1(-137.175,103.8) -142.2,103.8 -143,103 -143,100 -145.5,97.5 -145.5,94.374 -150.374,89.5 -159.175,89.5 -163.337,85.337 ; v1(-135.8,101.8) -133.329,99.329 -133.304,99.329 -132.321,98.346 -132.321,98.321 -129.5,95.5 -115,95.5 ; v1(-116.404,89.48) -116.404,90.999 -114.403,93 -114.403,94.4 -114.707,94.4 -115,94.693 -115,95.5 ; -113.5,97 -115,95.5 ; v1@-47.04,111.973 v1(-47.04,111.971) -46.29,111.221 v1(-40.54,111.221) ; v1(-32.09,70.921) v1(-32.09,102.571)
  other v1: -40.971,25.649 -40.221,25.649 -40.971,27.149 -40.128,27.178
12V_SW1: C11.1 C16.2 C17.2 C19.2 C20.1 C24.1 C40.1 D1.1 D2.1 R12.1 U2.44 U3.28 U3.29 U4.44 | length 69.5
  Top Layer w0.5: U3.29@-119.5,105.6 -119.475,105.6 -119.45,105.575 U3.28@-119.45,105 ; U3.28@-119.475,104.975 C19.2@-112.525,104.975 ; R12.1@-115.675,106.825 -113.5,106.825 -112.625,105.95 C19.2@-112.625,105.375 ; C19.2@-112.475,105.125 -99.098,105.125 -98.502,104.529 v1(-98.5,104.529) ; D1.1@-98.425,91.225 -97.738,91.912 -96.888,91.912 -95.775,93.025 -92.893,93.025 -92.6,93.318 -92.6,95.55 C11.1@-92.75,95.7 ; C40.1@-96.45,118.25 -94.734,118.25 -94.604,118.38 v1(-94.602,118.38) -94.481,118.26 -93.745,118.26 -93.537,118.053 D2.1@-93.537,117.9 ; v1(-93.725,111.1) -93.15,110.525 -92.9,110.525 -92.875,110.5 C24.1@-92.875,110.025 ; v1@-93.6,96.925 -93.6,96.118 -93.307,95.825 C11.1@-92.875,95.825 ; C24.1@-92.6,109.975 C24.1@-92.5,109.875
  Layer 1 w0.5: v1(-94.602,118.38) -94.602,111.979 v1@-93.722,111.1 ; v1(-93.725,111.1) -94.9,111.1 -96.971,109.029 -96.971,108.254 -98.5,106.725 -98.5,102.061 -93.654,97.215 -93.654,97.006 -93.575,96.927 v1(-93.575,96.925)
  Bottom Layer w0.25: U2.44@-93.8,96.325 v1@-93.8,96.841
  Bottom Layer w0.5: U2.44@-93.8,96 U2.44@-93.8,96.325 ; U4.44@-93.74,110.55 -93.74,110.937 -93.727,110.95 -93.727,111.098 v1(-93.725,111.1)
12V_SW2: C57.1 C62.2 C63.2 C65.1 C69.1 C188.1 C240.1 D7.1 D8.1 R45.1 U9.44 U10.28 U10.29 U11.44 | length 66.6
  Top Layer w0.5: D8.1@-63.503,115.971 -63.503,117.815 -62.318,119 D7.1@-58.45,119 ; C69.1@-63.34,99.171 -63.34,98.921 -63.04,98.621 -62.715,98.621 v1@-61.915,97.821 ; D8.1@-63.332,115.891 -63.54,115.683 -63.54,114.746 -63.483,114.688 -63.483,113.688 C57.1@-63.265,113.471 -63.265,113.221 -62.965,112.921 -62.494,112.921 -61.536,111.963 -61.536,111.918 -61.533,111.915 -61.344,111.915 -60.615,111.186 -60.615,111.165 -55.782,106.332 ; v1(-61.89,97.746) -61.036,96.892 -61.036,95.967 v1(-61.015,95.946) ; v1@-58.44,94.296 -56.74,92.596 -56.74,91.696 -56.515,91.471 R45.1@-56.49,91.471 -56.49,92.646 -56.115,93.021 -54.94,93.021 -54.915,92.996 C65.1@-54.915,92.896 ; v1@-58.011,101.542 -59.49,103.021 -59.49,105.521 -58.679,106.332 -55.782,106.332 ; v1(-55.526,106.332) -55.782,106.332 ; U10.29@-55.24,87.696 U10.28@-54.615,87.696 ; C188.1@-54.873,94.579 -54.873,92.929 C65.1@-54.815,92.871 C62.2@-54.815,89.846 ; C62.2@-54.815,89.696 -54.815,88.771 U10.28@-54.64,88.596 ; v1(-52.326,104.432) -52.324,104.43 -51.483,104.43 -51.483,103.671 -51.233,103.421 C240.1@-51.19,103.421
  Layer 1 w0.5: v1(-61.015,95.946) -59.411,94.342 -58.511,94.342 v1(-58.49,94.321) -58.461,94.321 -57.69,95.091 -57.69,101.191 -57.99,101.491 v1(-57.99,101.521) ; v1(-55.526,106.332) -53.615,104.421 v1@-52.29,104.421
  Bottom Layer w0.25: U9.44@-62.275,112.996 -62.205,112.926 -62.205,112.264 -61.908,111.966 -61.584,111.966 v1(-61.535,111.917)
  Bottom Layer w0.5: U11.44@-62.275,98.746 -62.25,98.721 -62.25,98.034 v1@-61.987,97.771
AC_L: F1.2 J9.1 TP4.1
  other v1: -267.8,143.5 -266.8,143.5 -265.8,143.5 -264.8,143.5 -263.8,143.5 -267.8,144.5 -266.8,144.5 -265.8,144.5 -264.8,144.5 -263.8,144.5 -267.8,145.5 -266.8,145.5 -265.8,145.5 -264.8,145.5 -263.8,145.5 -267.8,146.5 -266.8,146.5 -265.8,146.5 -264.8,146.5 -263.8,146.5 -267.8,147.5 -266.8,147.5 -265.8,147.5 -264.8,147.5 -263.8,147.5 -267.8,148.5 -266.8,148.5 -265.8,148.5 -264.8,148.5 -263.8,148.5
AC_N: F2.2 J1.1 TP7.1
  other v1: -268,127 -267,127 -266,127 -265,127 -264,127 -263,127 -262,127 -261,127 -268,128 -267,128 -266,128 -265,128 -264,128 -268,129 -267,129 -266,129 -265,129 -264,129 -268,130 -267,130 -266,130 -265,130 -264,130 -268,131 -267,131 -266,131 -265,131 -264,131 -268,132 -267,132 -266,132 -265,132 -264,132 -264,133 -263,133 -262,133 -261,133
ACLOAD_L: J3.1 K1.2 R75.2 U16.2
  other v1: -196.9,125.4 -195.9,125.4 -194.9,125.4 -193.9,125.4 -196.9,126.4 -195.9,126.4 -194.9,126.4 -193.9,126.4 -196.9,127.4 -195.9,127.4 -194.9,127.4 -193.9,127.4 -204,132 -203,132 -204,133 -203,133 -204,134 -203,134 -204,135 -203,135 -204,136 -203,136 -204,137 -203,137 -180.699,166.454 -179.699,166.454 -178.699,166.454 -177.699,166.454 -176.699,166.454 -180.699,167.454 -179.699,167.454 -178.699,167.454 -177.699,167.454 -176.699,167.454 -180.699,168.454 -179.699,168.454 -178.699,168.454 -177.699,168.454 -176.699,168.454
ACLOAD_N: C104.1 C106.2 J32.1 K2.3 L10.EI R114.2 R122.1 | length 92.1
  Top Layer w0.25: R122.1@-171.345,125.882 -171.345,129.315 -168.707,131.953 -164.841,131.953 L10.EI@-164.793,131.905
  Layer 1 w0.5: J32.1@-164.639,171.425 -160.575,171.425 -157,175 -143,175 -141,177 -92,177 -89.879,174.879 C106.2@-86.86,174.879
  other v1: -208.9,163 -207.9,163 -206.9,163 -205.9,163 -204.9,163 -208.9,164 -207.9,164 -206.9,164 -205.9,164 -204.9,164 -208.9,165 -207.9,165 -206.9,165 -205.9,165 -204.9,165 -208.9,166 -207.9,166 -206.9,166 -205.9,166 -204.9,166 -166.699,167.454 -165.699,167.454 -164.699,167.454 -163.699,167.454 -162.699,167.454 -166.699,168.454 -165.699,168.454 -164.699,168.454 -163.699,168.454 -162.699,168.454 -166.699,169.454 -165.699,169.454 -164.699,169.454 -163.699,169.454 -162.699,169.454
  other v2: -166.752,128.664 -165.552,128.664 -164.352,128.664 -163.152,128.664 -168.552,129.864 -167.352,129.864 -166.152,129.864 -164.952,129.864 -163.752,129.864 -162.552,129.864 -167.952,131.064 -166.752,131.064 -163.152,131.064 -161.952,131.064 -160.752,131.064 -162.552,132.264 -161.352,132.264 -160.152,132.264 -163.152,133.464 -161.952,133.464 -160.752,133.464 -163.752,134.664 -162.552,134.664 -161.352,134.664 -160.152,134.664
Batt_H1: R200.1 R270.1 | length 66.4
  Top Layer w0.25: v1@-203,76.1 v1(-202.975,76.125) -202.975,77.25 R200.1@-203,77.275 ; v1(-197.6,71) -197.555,70.955 -197.555,69.955 -196.771,69.171 -192.609,69.171 -192.605,69.175 -189.865,69.175 -189.44,69.6 v1(-189.4,69.6) ; v1(-146.7,64.025) -145.625,64.025 R270.1@-145.575,63.975
  Layer 2 w0.25: v1(-189.4,69.6) -188.529,69.6 -187.429,68.5 -183.673,68.5 -182.295,69.878 -168.622,69.878 -166.995,68.25 -166.945,68.2 -150.898,68.2 -146.723,64.025 v1(-146.7,64.025)
  Bottom Layer w0.25: v1(-202.975,76.125) -202.926,76.076 -202.926,74.926 -199,71 v1(-197.6,71)
Batt_H1_Buff: J12.7 R272.2 | length 14.5
  Top Layer w0.25: v1@-142.675,62.2 -142.65,62.175 v1(-142.575,62.175) -141.547,62.175 R272.2@-141.467,62.095
  Layer 2 w0.25: v1@-142.525,62.125 -139.905,59.505 -135.44,59.505 J12.7@-131.825,55.89
Batt_H2: R195.2 R278.1 | length 93.9
  Top Layer w0.25: v1@-201.1,76.1 -201.05,76.15 R195.2@-201.05,77.275 ; R278.1@-124,66.4 v1(-123.2,66.4)
  Layer 2 w0.25: v1(-201.075,76.15) -199.135,74.21 -183.51,74.21 -181.421,72.121 -161.848,72.121 -160.998,71.271 -152.629,71.271 v1@-152.6,71.3 ; v1(-123.2,66.4) -122.521,65.721 -122.521,60.679 v1(-123,60.2)
  Bottom Layer w0.25: v1(-152.5,71.3) -140.705,59.505 -133.443,59.505 -133.173,59.775 -125.709,59.775 -125.705,59.771 -123.461,59.771 -123.032,60.2 v1(-123,60.2)
Batt_H2_Buff: J12.11 R284.2 | length 17.9
  Top Layer w0.25: R284.2@-128.075,64.525 -128,64.6 v1(-127.05,64.6)
  Layer 2 w0.25: v1(-127.05,64.6) -125.425,62.975 v1@-125.425,58.95
  Bottom Layer w0.25: J12.11@-134.365,55.89 -130.88,59.375 -125.875,59.375 v1(-125.45,58.95)
Batt_L1: R201.1 R274.1 | length 91.3
  Top Layer w0.25: v1(-203.2,71.1) -203.2,73.1 -202.95,73.35 R201.1@-202.225,73.35 ; v1(-192.525,69.75) -192,70.275 -177.925,70.275 v1@-175.6,72.6 ; R274.1@-124.135,62.603 -124.113,62.625 -123.15,62.625 v1@-123.05,62.525
  Layer 2 w0.25: v1(-203.2,71.1) -200.8,68.7 -193.7,68.7 v1@-192.6,69.8 ; v1@-175.5,72.7 -153.152,72.7 -152.152,71.7 v1(-147.7,71.7)
  Bottom Layer w0.25: v1(-147.7,71.7) -146.554,70.554 -142.131,70.554 -133.773,62.196 -123.511,62.196 -123.082,62.625 v1(-123.05,62.625)
  other v1: -175.525,72.65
